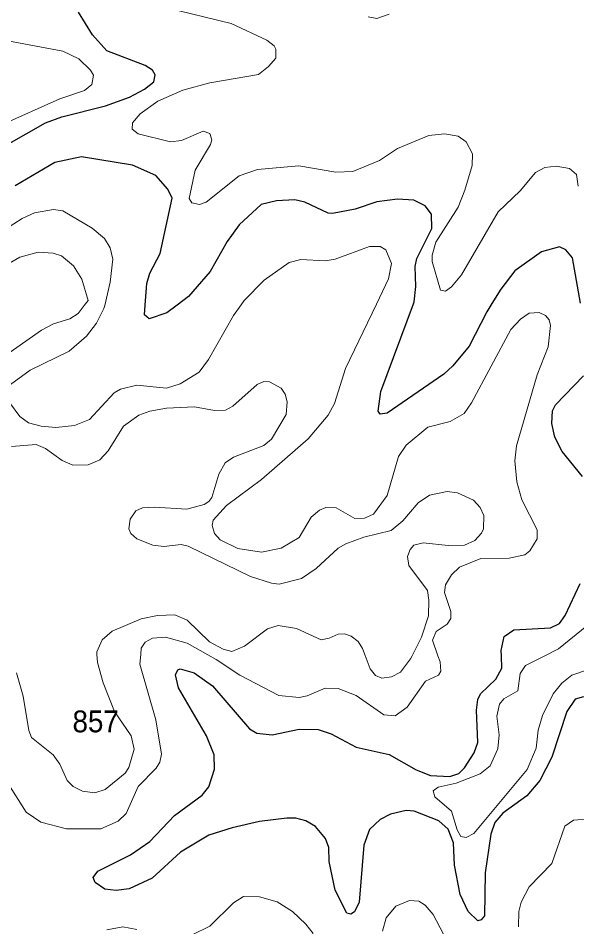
# Model space of a CAD drawing. Extents: x 473.9 to 500, y 7733.1 to 7760.8.
# Drawn here: x 494.35 to 496.397, y 7740.071 to 7743.401 of the extents above; entities that cross this region are included whole.
import ezdxf

# ---------------------------------------------------------------- set-up
doc = ezdxf.new("R2010")
doc.units = 0
doc.header["$LTSCALE"] = 0.032
doc.layers.add('1', color=7, linetype='Continuous', lineweight=25)
doc.layers.add('2', color=7, linetype='Continuous', lineweight=13)
doc.layers.add('21', color=7, linetype='Continuous')

msp = doc.modelspace()

# ---------------------------------------------------------------- linework, layer by layer
at = {"layer": '1'}
for points in [[(494.8153, 7743.2279), (494.6753, 7743.2812), (494.6224, 7743.3404), (494.5707, 7743.4231)], [(494.3083, 7742.9374), (494.4501, 7743.0182), (494.5105, 7743.0399), (494.6696, 7743.0802), (494.7577, 7743.1116), (494.8126, 7743.1415), (494.8471, 7743.1686), (494.8523, 7743.1934), (494.8424, 7743.2102), (494.8153, 7743.2279)], [(496.4101, 7742.3567), (496.3808, 7742.5231), (496.3573, 7742.5519), (496.333, 7742.5628), (496.2681, 7742.5447), (496.1703, 7742.4747), (496.119, 7742.4077), (496.086, 7742.3552), (496.0671, 7742.3252), (496.002, 7742.199), (495.9427, 7742.1268), (495.9093, 7742.0967), (495.7019, 7741.954), (495.6759, 7741.9504), (495.6694, 7741.9612), (495.6792, 7742.0328), (495.7983, 7742.3539), (495.801, 7742.3613), (495.8074, 7742.4179), (495.8043, 7742.4915), (495.8104, 7742.5209), (495.8654, 7742.6304), (495.864, 7742.6826), (495.8419, 7742.7134), (495.7998, 7742.7338), (495.7399, 7742.7383), (495.6637, 7742.7277), (495.5845, 7742.7015), (495.5023, 7742.6853), (495.4859, 7742.6868), (495.4002, 7742.7275), (495.3636, 7742.7359), (495.2963, 7742.7323), (495.2402, 7742.7182), (495.1604, 7742.6434), (495.1156, 7742.5829), (495.0533, 7742.4723), (494.9745, 7742.3815), (494.9331, 7742.3499), (494.8954, 7742.3212), (494.8307, 7742.2995), (494.8131, 7742.3141), (494.8158, 7742.3494), (494.8219, 7742.4294), (494.8331, 7742.4671), (494.871, 7742.5387), (494.9149, 7742.7414), (494.8989, 7742.7745), (494.855, 7742.8245), (494.7687, 7742.8621), (494.5826, 7742.8926), (494.4843, 7742.8718), (494.3388, 7742.7864)], [(496.4177, 7741.7208), (496.3434, 7741.8135), (496.3159, 7741.8655), (496.306, 7741.9152), (496.308, 7741.962), (496.3185, 7741.9843), (496.4214, 7742.0908)], [(495.9647, 7740.6321), (495.9851, 7740.6533), (496.0203, 7740.7088), (496.034, 7740.7462), (496.0293, 7740.8645), (496.0344, 7740.9044), (496.0444, 7740.9247), (496.1001, 7740.9789), (496.1224, 7741.0189), (496.1205, 7741.0628), (496.1196, 7741.0835), (496.1302, 7741.1345), (496.1657, 7741.1587), (496.3005, 7741.167), (496.3337, 7741.1823), (496.3542, 7741.2116), (496.4091, 7741.3295)], [(496.4217, 7740.9131), (496.3913, 7740.9056), (496.3604, 7740.8604), (496.3049, 7740.6931), (496.2609, 7740.6065), (496.2141, 7740.5505), (496.1253, 7740.4872), (496.0963, 7740.453), (496.0822, 7740.4105), (496.0616, 7740.2683), (496.0592, 7740.1108), (496.047, 7740.0965), (496.0339, 7740.0931), (495.9989, 7740.1272), (495.9693, 7740.1889), (495.9482, 7740.2965), (495.9449, 7740.3786), (495.9254, 7740.4288), (495.8919, 7740.4588), (495.801, 7740.4943), (495.7715, 7740.4966), (495.7139, 7740.4835), (495.6762, 7740.4646), (495.6379, 7740.4272), (495.6169, 7740.3699), (495.5993, 7740.1606), (495.5828, 7740.125), (495.5689, 7740.1169), (495.5547, 7740.1202), (495.5111, 7740.205), (495.4893, 7740.3097), (495.4881, 7740.3615), (495.4762, 7740.3946), (495.4395, 7740.4384), (495.4043, 7740.4586), (495.3669, 7740.4683), (495.3341, 7740.4694), (495.2339, 7740.457), (495.1337, 7740.434), (495.0484, 7740.4064), (494.945, 7740.3448), (494.841, 7740.2492), (494.7564, 7740.2096), (494.709, 7740.2033), (494.668, 7740.2091), (494.6325, 7740.2326), (494.625, 7740.2509), (494.6423, 7740.2742), (494.7612, 7740.3347), (494.832, 7740.3834), (494.9233, 7740.4784), (495.0243, 7740.5531), (495.0485, 7740.5835), (495.0691, 7740.6491), (495.0683, 7740.7009), (495.0396, 7740.7709), (494.9381, 7740.9468), (494.9265, 7740.9944), (494.9351, 7741.0125), (494.9434, 7741.0159), (494.9955, 7741.0016), (495.0616, 7740.9541), (495.1983, 7740.7958), (495.2249, 7740.7804), (495.281, 7740.774), (495.3798, 7740.795), (495.4496, 7740.7941), (495.4975, 7740.7778), (495.5885, 7740.7287), (495.7094, 7740.7025), (495.8081, 7740.6461), (495.8605, 7740.6255), (495.9319, 7740.6216), (495.9647, 7740.6321)]]:
    msp.add_lwpolyline(points, dxfattribs=at)
at = {"layer": '2'}
for points in [[(494.8899, 7743.4409), (495.1311, 7743.3821), (495.2612, 7743.3203), (495.2881, 7743.3001)], [(495.7091, 7743.4155), (495.6648, 7743.4001), (495.6322, 7743.4066)], [(494.2718, 7743.3253), (494.5144, 7743.28), (494.5729, 7743.2525), (494.6154, 7743.2108), (494.6257, 7743.1927), (494.6195, 7743.158), (494.5929, 7743.1361), (494.5034, 7743.1058), (494.2825, 7743.0082)], [(495.2881, 7743.3001), (495.2939, 7743.2874), (495.2939, 7743.2542), (495.2679, 7743.2239), (495.2307, 7743.1954), (495.0521, 7743.1643), (494.9532, 7743.1376), (494.862, 7743.0967), (494.7967, 7743.0508), (494.7693, 7743.0179), (494.7673, 7742.995), (494.7898, 7742.9779), (494.908, 7742.9476), (494.9481, 7742.953), (495.0276, 7742.9872), (495.0526, 7742.9789), (495.0597, 7742.9558), (495.0552, 7742.9387), (494.9987, 7742.8437), (494.9769, 7742.74), (494.9866, 7742.7242), (495.0143, 7742.7184), (495.0393, 7742.7275), (495.1595, 7742.8236), (495.227, 7742.8469), (495.378, 7742.8606), (495.5136, 7742.8374), (495.5758, 7742.8393), (495.674, 7742.8796), (495.74, 7742.9232), (495.8552, 7742.9712), (495.9124, 7742.978), (495.9621, 7742.9694), (495.9915, 7742.9475), (496.0148, 7742.9043), (496.013, 7742.8619), (495.9869, 7742.7711), (495.962, 7742.7092), (495.8808, 7742.58), (495.8668, 7742.5321), (495.8673, 7742.509), (495.8977, 7742.4046), (495.9161, 7742.4007), (495.9381, 7742.4164), (495.9745, 7742.4601), (496.109, 7742.6909), (496.1898, 7742.7685), (496.2456, 7742.8358), (496.2802, 7742.8541), (496.321, 7742.8589), (496.3703, 7742.8509), (496.3961, 7742.8284), (496.4025, 7742.7857)], [(494.2718, 7742.609), (494.3649, 7742.6668), (494.4096, 7742.6875), (494.4795, 7742.7005), (494.5134, 7742.6954), (494.6213, 7742.6321), (494.6662, 7742.5933), (494.6872, 7742.559), (494.6972, 7742.5184), (494.6874, 7742.4331), (494.6673, 7742.3487), (494.6646, 7742.3376), (494.6375, 7742.284), (494.601, 7742.2354), (494.5376, 7742.1807), (494.3935, 7742.1116), (494.3217, 7742.0583)], [(494.3564, 7741.9407), (494.3884, 7741.9183), (494.4343, 7741.9059), (494.4881, 7741.9008), (494.557, 7741.9088), (494.612, 7741.9303), (494.7022, 7742.0279), (494.7248, 7742.041), (494.7849, 7742.0566), (494.8937, 7742.0455), (494.9441, 7742.0611), (495.0131, 7742.1041), (495.0475, 7742.1501), (495.1386, 7742.3114), (495.1668, 7742.351), (495.178, 7742.3667), (495.2515, 7742.4412), (495.3428, 7742.506), (495.3862, 7742.5172), (495.4752, 7742.5116), (495.5114, 7742.5176), (495.6376, 7742.5648), (495.676, 7742.5649), (495.6977, 7742.5526), (495.7174, 7742.5024), (495.7075, 7742.4457), (495.6631, 7742.3533), (495.5497, 7742.1174), (495.5088, 7741.9893), (495.4855, 7741.9459), (495.4122, 7741.8591), (495.2418, 7741.7105), (495.114, 7741.6155), (495.0649, 7741.5611), (495.0615, 7741.5416), (495.0697, 7741.5121), (495.0906, 7741.4895), (495.1549, 7741.458), (495.2418, 7741.444), (495.3133, 7741.4581), (495.3801, 7741.4973), (495.424, 7741.5717), (495.4537, 7741.5979), (495.4768, 7741.608), (495.515, 7741.6067), (495.5834, 7741.5678), (495.6192, 7741.569), (495.6519, 7741.583), (495.7015, 7741.6511), (495.7435, 7741.7941), (495.7718, 7741.8363), (495.8517, 7741.9016), (495.9334, 7741.9227), (495.9847, 7741.9517), (496.0114, 7741.9909), (496.1549, 7742.26), (496.1902, 7742.2977), (496.2221, 7742.3197), (496.2592, 7742.3229), (496.2821, 7742.3121), (496.2953, 7742.2952), (496.3003, 7742.2748), (496.2916, 7742.1962), (496.2511, 7742.0938), (496.1758, 7741.8338), (496.1702, 7741.7787), (496.177, 7741.7023), (496.1952, 7741.6355), (496.2513, 7741.5263), (496.2512, 7741.493), (496.2251, 7741.4485), (496.2062, 7741.4346), (496.1495, 7741.4215), (496.0456, 7741.4205), (495.9673, 7741.3887), (495.9372, 7741.3609), (495.9163, 7741.3247), (495.912, 7741.2964), (495.9352, 7741.226), (495.9349, 7741.2003), (495.9223, 7741.1795), (495.8816, 7741.1528), (495.8687, 7741.1215), (495.8882, 7741.0639), (495.8958, 7741.0416), (495.8982, 7741.0074), (495.8896, 7740.9936), (495.8427, 7740.9705), (495.7757, 7740.8759), (495.7315, 7740.8443), (495.6901, 7740.8481), (495.5891, 7740.9183), (495.5223, 7740.9439), (495.4746, 7740.9453), (495.4093, 7740.917), (495.3795, 7740.911), (495.3053, 7740.9191), (495.1621, 7740.9931), (495.0752, 7741.0509), (495.0453, 7741.0678)], [(494.2125, 7742.4422), (494.3565, 7742.5249), (494.4235, 7742.5439), (494.4787, 7742.5406), (494.5083, 7742.5308), (494.5524, 7742.4939), (494.5837, 7742.4449), (494.6062, 7742.3671), (494.5922, 7742.3484), (494.5701, 7742.3188), (494.5393, 7742.2997), (494.4798, 7742.2813), (494.4359, 7742.2575), (494.2877, 7742.1539)], [(494.416, 7741.8391), (494.4508, 7741.8238), (494.5109, 7741.7796), (494.5505, 7741.7632), (494.6062, 7741.7636), (494.6498, 7741.7826), (494.6795, 7741.8156), (494.7362, 7741.9058), (494.7923, 7741.9462), (494.832, 7741.9614), (494.8936, 7741.9713), (494.9956, 7741.9762), (495.0692, 7741.963), (495.1102, 7741.9647), (495.1366, 7741.9796), (495.2255, 7742.0588), (495.2504, 7742.0697), (495.2709, 7742.0688), (495.3138, 7742.0453), (495.3283, 7742.0236), (495.3363, 7741.9946), (495.3322, 7741.9482), (495.2784, 7741.858), (495.2502, 7741.8349), (495.139, 7741.7923), (495.1086, 7741.771), (495.0855, 7741.7304), (495.0599, 7741.6447), (495.0492, 7741.6292), (495.0322, 7741.619), (494.9676, 7741.6017), (494.8491, 7741.6095), (494.8062, 7741.6061), (494.7809, 7741.5957), (494.7607, 7741.5646), (494.7551, 7741.529), (494.7624, 7741.5122), (494.7853, 7741.4927), (494.8438, 7741.4698), (494.8842, 7741.4648), (494.9478, 7741.4719), (494.9734, 7741.4659), (495.2018, 7741.3553), (495.2784, 7741.3298), (495.3064, 7741.3266), (495.3879, 7741.3471), (495.4422, 7741.384), (495.522, 7741.4584), (495.5505, 7741.4749), (495.6167, 7741.4986), (495.717, 7741.5237), (495.7596, 7741.5592), (495.8155, 7741.6248), (495.8568, 7741.6526), (495.9218, 7741.6659), (495.9602, 7741.661), (496.0181, 7741.6344), (496.0427, 7741.6076), (496.0557, 7741.5788), (496.0551, 7741.53), (496.048, 7741.5133), (496.0229, 7741.4873), (495.9854, 7741.47), (495.9254, 7741.4681), (495.8338, 7741.4776), (495.7996, 7741.4691), (495.786, 7741.454), (495.777, 7741.4286), (495.7815, 7741.3953), (495.8493, 7741.303), (495.8549, 7741.2678), (495.8533, 7741.21), (495.8282, 7741.1323), (495.7936, 7741.0644), (495.7877, 7741.0528), (495.7513, 7741.0042), (495.718, 7740.9866), (495.683, 7740.9817), (495.6588, 7740.9916), (495.6403, 7741.0169), (495.6214, 7741.0651), (495.6115, 7741.0904), (495.5953, 7741.1159), (495.5698, 7741.1362), (495.5454, 7741.1442), (495.5223, 7741.1431), (495.4897, 7741.1284), (495.4597, 7741.123), (495.3696, 7741.1642), (495.3031, 7741.1754), (495.264, 7741.1633), (495.1793, 7741.0991), (495.1335, 7741.0804), (495.101, 7741.088), (495.0516, 7741.1157), (494.9698, 7741.195), (494.9247, 7741.2147), (494.8603, 7741.2123), (494.8013, 7741.1995), (494.6943, 7741.1541)], [(494.3188, 7741.9922), (494.3564, 7741.9407)], [(494.3255, 7741.8307), (494.416, 7741.8391)], [(494.6943, 7741.1541), (494.6577, 7741.1223), (494.6378, 7741.0781), (494.6384, 7741.0697), (494.6404, 7741.04), (494.6615, 7740.965), (494.7037, 7740.8595), (494.764, 7740.7704), (494.7751, 7740.7216), (494.756, 7740.6541), (494.7418, 7740.6339), (494.6689, 7740.5741), (494.631, 7740.5612), (494.5854, 7740.5684), (494.5511, 7740.5854), (494.5301, 7740.6072), (494.5033, 7740.6664), (494.4785, 7740.7013), (494.3986, 7740.764), (494.389, 7740.7898), (494.3687, 7740.9157), (494.3441, 7741.0015)], [(496.4334, 7741.1741), (496.3293, 7741.0899), (496.2749, 7741.0621), (496.2091, 7741.0286), (496.1893, 7740.9987), (496.1808, 7740.9357), (496.1301, 7740.9059), (496.1133, 7740.8865), (496.1034, 7740.8429), (496.1129, 7740.7741), (496.1073, 7740.7228), (496.0795, 7740.6606), (496.0423, 7740.632), (495.9543, 7740.5977), (495.889, 7740.5826), (495.8707, 7740.5689), (495.8772, 7740.5465), (495.9376, 7740.4948), (495.9591, 7740.4257), (495.9725, 7740.4015), (495.9919, 7740.3979), (496.0202, 7740.4127), (496.2147, 7740.6467), (496.2478, 7740.7254), (496.2558, 7740.7916), (496.2714, 7740.8458), (496.3107, 7740.9248), (496.3417, 7740.9635), (496.3789, 7740.9931), (496.4324, 7741.0112)], [(495.0453, 7741.0678), (494.9689, 7741.111), (494.8904, 7741.132), (494.8421, 7741.1293), (494.815, 7741.1143), (494.8014, 7741.0919), (494.7993, 7741.0689), (494.7961, 7741.0336), (494.8545, 7740.8293), (494.8748, 7740.7034), (494.8691, 7740.6737), (494.8556, 7740.6517), (494.7893, 7740.5847), (494.7454, 7740.4863), (494.716, 7740.4579), (494.653, 7740.4301), (494.5275, 7740.4293), (494.4336, 7740.4546), (494.3795, 7740.4912), (494.312, 7740.5973)], [(496.1838, 7740.0702), (496.1844, 7740.1265), (496.1931, 7740.1604), (496.2224, 7740.2178), (496.3059, 7740.3028), (496.3535, 7740.439), (496.3854, 7740.4615), (496.4501, 7740.467)], [(494.9875, 7740.0416), (495.052, 7740.0731), (495.1394, 7740.159), (495.1758, 7740.1814), (495.2344, 7740.1802), (495.2989, 7740.1626), (495.3553, 7740.1265), (495.4043, 7740.0804), (495.4312, 7740.0458)], [(495.6854, 7740.0549), (495.6983, 7740.1036), (495.7338, 7740.1468), (495.7838, 7740.1677), (495.8176, 7740.1642), (495.8412, 7740.1494), (495.8709, 7740.1155), (495.9465, 7739.9717)], [(494.6744, 7740.0597), (494.7339, 7740.0706), (494.7853, 7740.0613)]]:
    msp.add_lwpolyline(points, dxfattribs=at)

# ---------------------------------------------------------------- texts
at = {"layer": '21', "width": 0.95}
msp.add_text('857', height=0.08, dxfattribs=at).set_placement((494.5493, 7740.7836))

doc.saveas('drawing.dxf')
